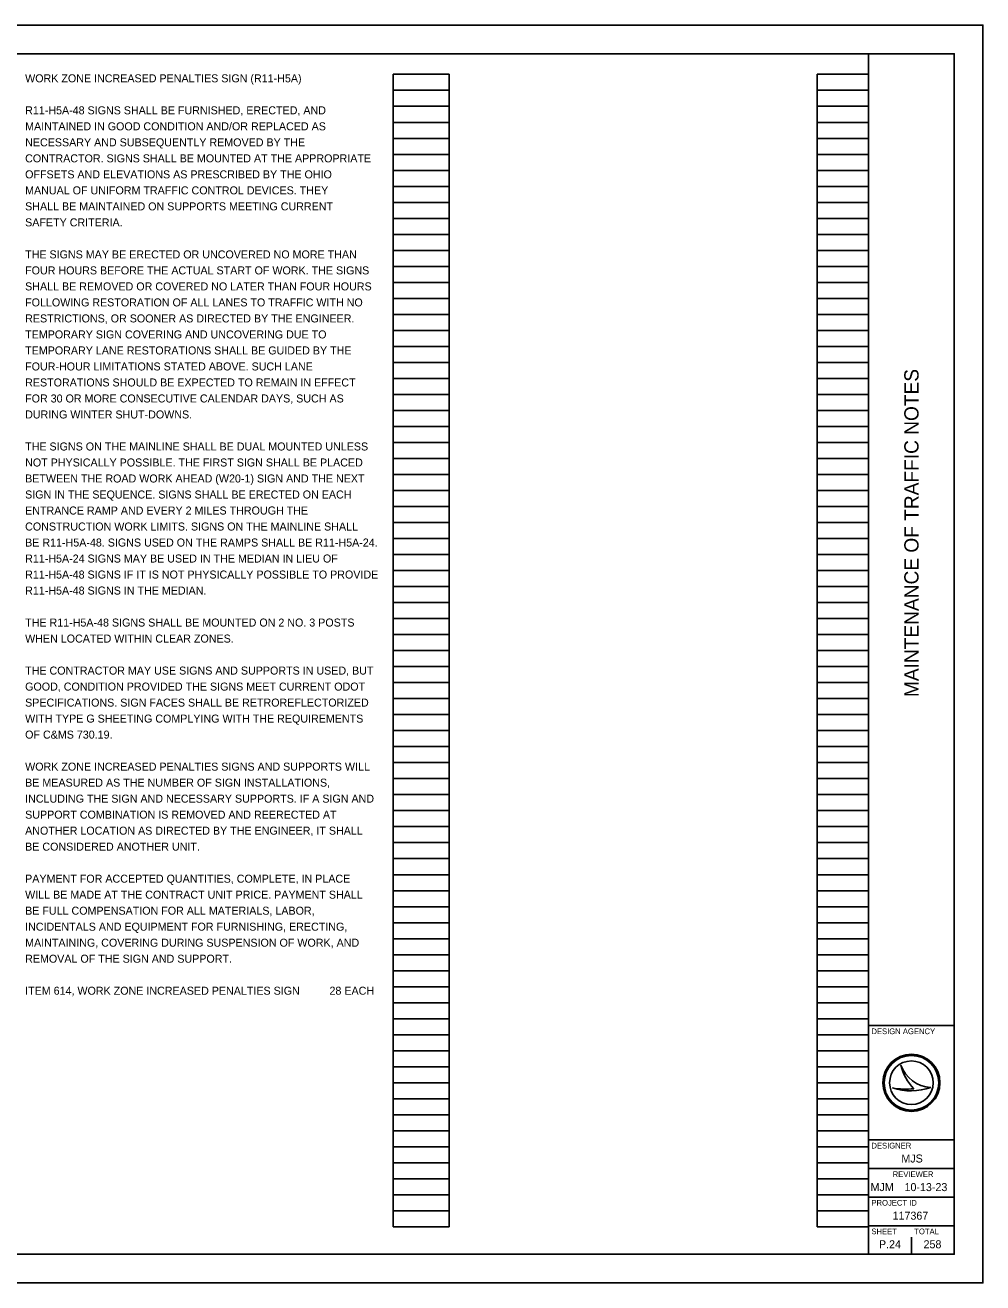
# Model space of a CAD drawing. Extents: x 0 to 34, y -6.1 to 22.
# Drawn here: x 17.24 to 34, y 0 to 22 of the extents above; entities that cross this region are included whole.
import ezdxf

# ---------------------------------------------------------------- set-up
doc = ezdxf.new("R2010")
doc.units = 0
for name, color, linetype in [('SH_Border', 7, 'Continuous'), ('SH_Cut_Line', 7, 'Continuous'), ('SH_Data', 7, 'Continuous'), ('SH_Text', 7, 'Continuous')]:
    doc.layers.add(name, color=color, linetype=linetype)

msp = doc.modelspace()

# ---------------------------------------------------------------- linework, layer by layer
at = {"layer": 'SH_Border'}
for p, q in [((32, 0.5), (32, 21.5)), ((32, 4.5), (33.5, 4.5)), ((32, 2.5), (33.5, 2.5)), ((32, 2), (33.5, 2)), ((32, 1.5), (33.5, 1.5)), ((32, 1), (33.5, 1))]:
    msp.add_line(p, q, dxfattribs=at)
msp.add_lwpolyline([(1.5, 21.5), (33.5, 21.5), (33.5, 0.5), (1.5, 0.5)], close=True, dxfattribs=at)
at = {"layer": 'SH_Cut_Line'}
msp.add_lwpolyline([(0, 0), (34, 0), (34, 22), (0, 22)], close=True, dxfattribs=at)
at = {"layer": 'SH_Data'}
for p, q in [((23.68, 0.98), (23.68, 21.14)), ((23.68, 21.14), (24.66, 21.14)), ((24.66, 0.98), (24.66, 21.14)), ((31.1, 0.98), (31.1, 21.14)), ((31.1, 21.14), (32, 21.14)), ((32, 0.98), (32, 21.14)), ((23.68, 20.86), (24.66, 20.86)), ((31.1, 20.86), (32, 20.86)), ((23.68, 20.58), (24.66, 20.58)), ((31.1, 20.58), (32, 20.58)), ((23.68, 20.3), (24.66, 20.3)), ((31.1, 20.3), (32, 20.3)), ((23.68, 20.02), (24.66, 20.02)), ((31.1, 20.02), (32, 20.02)), ((23.68, 19.74), (24.66, 19.74)), ((31.1, 19.74), (32, 19.74)), ((23.68, 19.46), (24.66, 19.46)), ((31.1, 19.46), (32, 19.46)), ((23.68, 19.18), (24.66, 19.18)), ((31.1, 19.18), (32, 19.18)), ((23.68, 18.9), (24.66, 18.9)), ((31.1, 18.9), (32, 18.9)), ((23.68, 18.62), (24.66, 18.62)), ((31.1, 18.62), (32, 18.62)), ((23.68, 18.34), (24.66, 18.34)), ((31.1, 18.34), (32, 18.34)), ((23.68, 18.06), (24.66, 18.06)), ((31.1, 18.06), (32, 18.06)), ((23.68, 17.78), (24.66, 17.78)), ((31.1, 17.78), (32, 17.78)), ((23.68, 17.5), (24.66, 17.5)), ((31.1, 17.5), (32, 17.5)), ((23.68, 17.22), (24.66, 17.22)), ((31.1, 17.22), (32, 17.22)), ((23.68, 16.94), (24.66, 16.94)), ((31.1, 16.94), (32, 16.94)), ((23.68, 16.66), (24.66, 16.66)), ((31.1, 16.66), (32, 16.66)), ((23.68, 16.38), (24.66, 16.38)), ((31.1, 16.38), (32, 16.38)), ((23.68, 16.1), (24.66, 16.1)), ((31.1, 16.1), (32, 16.1)), ((23.68, 15.82), (24.66, 15.82)), ((31.1, 15.82), (32, 15.82)), ((23.68, 15.54), (24.66, 15.54)), ((31.1, 15.54), (32, 15.54)), ((23.68, 15.26), (24.66, 15.26)), ((31.1, 15.26), (32, 15.26)), ((23.68, 14.98), (24.66, 14.98)), ((31.1, 14.98), (32, 14.98)), ((23.68, 14.7), (24.66, 14.7)), ((31.1, 14.7), (32, 14.7)), ((23.68, 14.42), (24.66, 14.42)), ((31.1, 14.42), (32, 14.42)), ((23.68, 14.14), (24.66, 14.14)), ((31.1, 14.14), (32, 14.14)), ((23.68, 13.86), (24.66, 13.86)), ((31.1, 13.86), (32, 13.86)), ((23.68, 13.58), (24.66, 13.58)), ((31.1, 13.58), (32, 13.58)), ((23.68, 13.3), (24.66, 13.3)), ((31.1, 13.3), (32, 13.3)), ((23.68, 13.02), (24.66, 13.02)), ((31.1, 13.02), (32, 13.02)), ((23.68, 12.74), (24.66, 12.74)), ((31.1, 12.74), (32, 12.74)), ((23.68, 12.46), (24.66, 12.46)), ((31.1, 12.46), (32, 12.46)), ((23.68, 12.18), (24.66, 12.18)), ((31.1, 12.18), (32, 12.18)), ((23.68, 11.9), (24.66, 11.9)), ((31.1, 11.9), (32, 11.9)), ((23.68, 11.62), (24.66, 11.62)), ((31.1, 11.62), (32, 11.62)), ((23.68, 11.34), (24.66, 11.34)), ((31.1, 11.34), (32, 11.34)), ((23.68, 11.06), (24.66, 11.06)), ((31.1, 11.06), (32, 11.06)), ((23.68, 10.78), (24.66, 10.78)), ((31.1, 10.78), (32, 10.78)), ((23.68, 10.5), (24.66, 10.5)), ((31.1, 10.5), (32, 10.5)), ((23.68, 10.22), (24.66, 10.22)), ((31.1, 10.22), (32, 10.22)), ((23.68, 9.94), (24.66, 9.94)), ((31.1, 9.94), (32, 9.94)), ((23.68, 9.66), (24.66, 9.66)), ((31.1, 9.66), (32, 9.66)), ((23.68, 9.38), (24.66, 9.38)), ((31.1, 9.38), (32, 9.38)), ((23.68, 9.1), (24.66, 9.1)), ((31.1, 9.1), (32, 9.1)), ((23.68, 8.82), (24.66, 8.82)), ((31.1, 8.82), (32, 8.82)), ((23.68, 8.54), (24.66, 8.54)), ((31.1, 8.54), (32, 8.54)), ((23.68, 8.26), (24.66, 8.26)), ((31.1, 8.26), (32, 8.26)), ((23.68, 7.98), (24.66, 7.98)), ((31.1, 7.98), (32, 7.98)), ((23.68, 7.7), (24.66, 7.7)), ((31.1, 7.7), (32, 7.7)), ((23.68, 7.42), (24.66, 7.42)), ((31.1, 7.42), (32, 7.42)), ((23.68, 7.14), (24.66, 7.14)), ((31.1, 7.14), (32, 7.14)), ((23.68, 6.86), (24.66, 6.86)), ((31.1, 6.86), (32, 6.86)), ((23.68, 6.58), (24.66, 6.58)), ((31.1, 6.58), (32, 6.58)), ((23.68, 6.3), (24.66, 6.3)), ((31.1, 6.3), (32, 6.3)), ((23.68, 6.02), (24.66, 6.02)), ((31.1, 6.02), (32, 6.02)), ((23.68, 5.74), (24.66, 5.74)), ((31.1, 5.74), (32, 5.74)), ((23.68, 5.46), (24.66, 5.46)), ((31.1, 5.46), (32, 5.46)), ((23.68, 5.18), (24.66, 5.18)), ((31.1, 5.18), (32, 5.18)), ((23.68, 4.9), (24.66, 4.9)), ((31.1, 4.9), (32, 4.9)), ((23.68, 4.62), (24.66, 4.62)), ((31.1, 4.62), (32, 4.62)), ((23.68, 4.34), (24.66, 4.34)), ((31.1, 4.34), (32, 4.34)), ((23.68, 4.06), (24.66, 4.06)), ((31.1, 4.06), (32, 4.06)), ((23.68, 3.78), (24.66, 3.78)), ((31.1, 3.78), (32, 3.78)), ((32.567, 3.81), (32.567, 3.81)), ((23.68, 3.5), (24.66, 3.5)), ((31.1, 3.5), (32, 3.5)), ((32.417, 3.41), (32.417, 3.41)), ((32.75, 3.5), (32.75, 3.5)), ((33.087, 3.419), (33.087, 3.419)), ((23.68, 3.22), (24.66, 3.22)), ((31.1, 3.22), (32, 3.22)), ((23.68, 2.94), (24.66, 2.94)), ((31.1, 2.94), (32, 2.94)), ((23.68, 2.66), (24.66, 2.66)), ((31.1, 2.66), (32, 2.66)), ((23.68, 2.38), (24.66, 2.38)), ((31.1, 2.38), (32, 2.38)), ((23.68, 2.1), (24.66, 2.1)), ((31.1, 2.1), (32, 2.1)), ((23.68, 1.82), (24.66, 1.82)), ((31.1, 1.82), (32, 1.82)), ((23.68, 1.54), (24.66, 1.54)), ((31.1, 1.54), (32, 1.54)), ((23.68, 1.26), (24.66, 1.26)), ((31.1, 1.26), (32, 1.26)), ((23.68, 0.98), (24.66, 0.98)), ((31.1, 0.98), (32, 0.98)), ((32.375, 0.675), (32.375, 0.675)), ((32.75, 0.5), (32.75, 0.8))]:
    msp.add_line(p, q, dxfattribs=at)
for radius in [0.5, 0.477, 0.477, 0.382]:
    msp.add_circle((32.75, 3.5), radius, dxfattribs=at)
for centre, radius, start, end in [((33.116, 3.998), 0.58, 198.9257, 198.9319), ((33.347, 3.97), 0.796, 191.6379, 191.6421), ((33.116, 3.998), 0.58, 198.9319, 267.1657), ((33.347, 3.97), 0.796, 191.6421, 226.0947), ((32.739, 4.37), 1.013, 251.4576, 290.0832), ((32.648, 4.654), 1.266, 259.4964, 259.4995), ((32.739, 4.37), 1.013, 251.4527, 251.4576), ((32.648, 4.654), 1.266, 259.4995, 276.6672)]:
    msp.add_arc(centre, radius, start, end, dxfattribs=at)

# ---------------------------------------------------------------- texts
msp.add_text('MAINTENANCE OF TRAFFIC NOTES', height=0.25, rotation=90, dxfattribs=at).set_placement((32.875, 10.247))
for s, height, p in [('DESIGN AGENCY', 0.1, (32.05, 4.35)), ('DESIGNER', 0.1, (32.05, 2.35)), ('MJS', 0.14, (32.574, 2.105)), ('REVIEWER', 0.1, (32.422, 1.85)), ('MJM', 0.14, (32.035, 1.605)), ('10-13-23', 0.14, (32.629, 1.605)), ('PROJECT ID', 0.1, (32.05, 1.35)), ('117367', 0.14, (32.42, 1.105)), ('SHEET', 0.1, (32.05, 0.85)), ('TOTAL', 0.1, (32.8, 0.85)), ('P.24', 0.14, (32.182, 0.605)), ('258', 0.14, (32.962, 0.605))]:
    msp.add_text(s, height=height, dxfattribs=at).set_placement(p)
at = {"layer": 'SH_Text'}
for s, p in [('WORK ZONE INCREASED PENALTIES SIGN (R11-H5A)', (17.24, 21)), ('R11-H5A-48 SIGNS SHALL BE FURNISHED, ERECTED, AND', (17.24, 20.44)), ('MAINTAINED IN GOOD CONDITION AND/OR REPLACED AS', (17.24, 20.16)), ('NECESSARY AND SUBSEQUENTLY REMOVED BY THE', (17.24, 19.88)), ('CONTRACTOR. SIGNS SHALL BE MOUNTED AT THE APPROPRIATE', (17.24, 19.6)), ('OFFSETS AND ELEVATIONS AS PRESCRIBED BY THE OHIO', (17.24, 19.32)), ('MANUAL OF UNIFORM TRAFFIC CONTROL DEVICES. THEY', (17.24, 19.04)), ('SHALL BE MAINTAINED ON SUPPORTS MEETING CURRENT', (17.24, 18.76)), ('SAFETY CRITERIA.', (17.24, 18.48)), ('THE SIGNS MAY BE ERECTED OR UNCOVERED NO MORE THAN', (17.24, 17.92)), ('FOUR HOURS BEFORE THE ACTUAL START OF WORK. THE SIGNS', (17.24, 17.64)), ('SHALL BE REMOVED OR COVERED NO LATER THAN FOUR HOURS', (17.24, 17.36)), ('FOLLOWING RESTORATION OF ALL LANES TO TRAFFIC WITH NO', (17.24, 17.08)), ('RESTRICTIONS, OR SOONER AS DIRECTED BY THE ENGINEER.', (17.24, 16.8)), ('TEMPORARY SIGN COVERING AND UNCOVERING DUE TO', (17.24, 16.52)), ('TEMPORARY LANE RESTORATIONS SHALL BE GUIDED BY THE', (17.24, 16.24)), ('FOUR-HOUR LIMITATIONS STATED ABOVE. SUCH LANE', (17.24, 15.96)), ('RESTORATIONS SHOULD BE EXPECTED TO REMAIN IN EFFECT', (17.24, 15.68)), ('FOR 30 OR MORE CONSECUTIVE CALENDAR DAYS, SUCH AS', (17.24, 15.4)), ('DURING WINTER SHUT-DOWNS.', (17.24, 15.12)), ('THE SIGNS ON THE MAINLINE SHALL BE DUAL MOUNTED UNLESS', (17.24, 14.56)), ('NOT PHYSICALLY POSSIBLE. THE FIRST SIGN SHALL BE PLACED', (17.24, 14.28)), ('BETWEEN THE ROAD WORK AHEAD (W20-1) SIGN AND THE NEXT', (17.24, 14)), ('SIGN IN THE SEQUENCE. SIGNS SHALL BE ERECTED ON EACH', (17.24, 13.72)), ('ENTRANCE RAMP AND EVERY 2 MILES THROUGH THE', (17.24, 13.44)), ('CONSTRUCTION WORK LIMITS. SIGNS ON THE MAINLINE SHALL', (17.24, 13.16)), ('BE R11-H5A-48. SIGNS USED ON THE RAMPS SHALL BE R11-H5A-24.', (17.24, 12.88)), ('R11-H5A-24 SIGNS MAY BE USED IN THE MEDIAN IN LIEU OF', (17.24, 12.6)), ('R11-H5A-48 SIGNS IF IT IS NOT PHYSICALLY POSSIBLE TO PROVIDE', (17.24, 12.32)), ('R11-H5A-48 SIGNS IN THE MEDIAN.', (17.24, 12.04)), ('THE R11-H5A-48 SIGNS SHALL BE MOUNTED ON 2 NO. 3 POSTS', (17.24, 11.48)), ('WHEN LOCATED WITHIN CLEAR ZONES.', (17.24, 11.2)), ('THE CONTRACTOR MAY USE SIGNS AND SUPPORTS IN USED, BUT', (17.24, 10.64)), ('GOOD, CONDITION PROVIDED THE SIGNS MEET CURRENT ODOT', (17.24, 10.36)), ('SPECIFICATIONS. SIGN FACES SHALL BE RETROREFLECTORIZED', (17.24, 10.08)), ('WITH TYPE G SHEETING COMPLYING WITH THE REQUIREMENTS', (17.24, 9.8)), ('OF C&MS 730.19.', (17.24, 9.52)), ('WORK ZONE INCREASED PENALTIES SIGNS AND SUPPORTS WILL', (17.24, 8.96)), ('BE MEASURED AS THE NUMBER OF SIGN INSTALLATIONS,', (17.24, 8.68)), ('INCLUDING THE SIGN AND NECESSARY SUPPORTS. IF A SIGN AND', (17.24, 8.4)), ('SUPPORT COMBINATION IS REMOVED AND REERECTED AT', (17.24, 8.12)), ('ANOTHER LOCATION AS DIRECTED BY THE ENGINEER, IT SHALL', (17.24, 7.84)), ('BE CONSIDERED ANOTHER UNIT.', (17.24, 7.56)), ('PAYMENT FOR ACCEPTED QUANTITIES, COMPLETE, IN PLACE', (17.24, 7)), ('WILL BE MADE AT THE CONTRACT UNIT PRICE. PAYMENT SHALL', (17.24, 6.72)), ('BE FULL COMPENSATION FOR ALL MATERIALS, LABOR,', (17.24, 6.44)), ('INCIDENTALS AND EQUIPMENT FOR FURNISHING, ERECTING,', (17.24, 6.16)), ('MAINTAINING, COVERING DURING SUSPENSION OF WORK, AND', (17.24, 5.88)), ('REMOVAL OF THE SIGN AND SUPPORT.', (17.24, 5.6)), ('ITEM 614, WORK ZONE INCREASED PENALTIES SIGN          28 EACH', (17.24, 5.04))]:
    msp.add_text(s, height=0.14, dxfattribs=at).set_placement(p)

doc.saveas('drawing.dxf')
